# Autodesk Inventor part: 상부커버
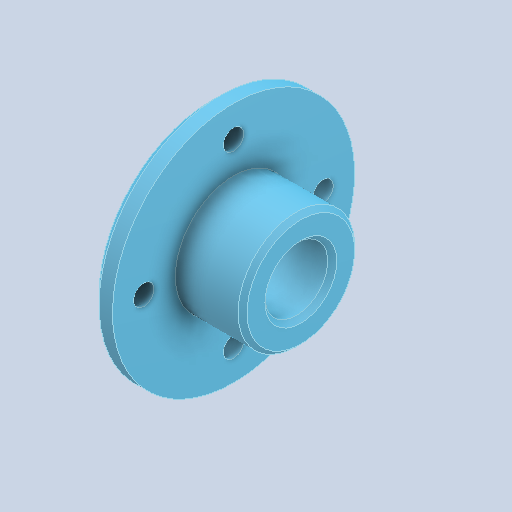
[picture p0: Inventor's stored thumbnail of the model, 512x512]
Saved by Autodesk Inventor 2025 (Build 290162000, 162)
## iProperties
Created: 2025-08
Part Number: 상부커버
Material: 알루미늄 6061
Document SubType Name: Modeling
Designer: infra02
Density: 2.71 g/cm^3
Appearance: 기본값
Sending System: Autodesk Inventor 2026
Preprocessor: ST-DEVELOPER v20.1
Author: jhkim
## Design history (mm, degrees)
feature "솔리드1"
node "솔리드2"
